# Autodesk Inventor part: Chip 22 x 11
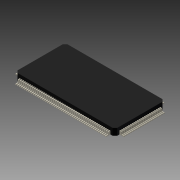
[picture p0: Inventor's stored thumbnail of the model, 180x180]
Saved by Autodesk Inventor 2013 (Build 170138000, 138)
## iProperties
Company: Autodesk Inc.
Created: 2005-12
Part Number: Chip 22 x 11
Document SubType Name: Modeling
Designer: Autodesk Inc.
Density: 1 g/cm^3
Mass: 0.375707 g
Surface Area: 7.692 cm^2
Volume: 0.375707 cm^3
Material: Allgemein
Title: Personal Computer
Author: Autodesk Inc.
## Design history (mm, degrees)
sketch "Sketch1"
  geometry: L1 (0, 7.7)-(0, -7.7) reference; L2 (-15.4, 0)-(15.4, 0) reference; L3 (-11, 5.5)-(11, 5.5); L4 (11, 5.5)-(11, -5.5); L5 (11, -5.5)-(-11, -5.5); L6 (-11, -5.5)-(-11, 5.5)
  constraints: 8 end point, 2 parallel, 1 horizontal, 1 perpendicular, 2 other
  dimensions: "d0" = 22 distance of L3.start L3.end; "d1" = 11 distance of L5.end L3.start
extrude "Extrusion1" new body sketch "Sketch1" distance "d2" = 1.5; taper "d3" = 0 deg
workplane "Work Plane1"
sketch "Sketch3"
  geometry: L1 (22, 0)-(22, 1.5) reference; L2 (22, 0)-(0, 0) reference; L3 (22, 0)-(23.221, 0); L4 (22, 0.75)-(22.317, 0.75); L5 (22.415, 0.668)-(22.485, 0.282); L6 (22.583, 0.2)-(22.85, 0.2); L7 (23, 0.05)-(23, 0); L8 (22, 0)-(23, 0); L9 (22, 0)-(22, 0.75); A1 r 0.1 centre (22.317, 0.65) between (22.415, 0.668) and (22.317, 0.75); A2 r 0.1 centre (22.583, 0.3) between (22.485, 0.282) and (22.583, 0.2); A3 r 0.15 centre (22.85, 0.05) between (23, 0.05) and (22.85, 0.2); 3 further points
  constraints: 14 end point, 7 point on line, 6 point on circle, 6 tangent, 3 centre point, 3 collinear, 2 parallel, 1 equal radius, 1 midpoint, 1 perpendicular
  dimensions: "d13" = 1 distance between parallel lines of L9 L7; "d14" = 0.4 distance of L4.start point (22.4, 0.75); "d15" = 0.2 distance of point (23, 0.2) L7.end; "d16" = 0.5 distance of point (22.5, 0.2) point (23, 0.2); "d17" = 0.1 radius of A1; "d18" = 0.15 radius of A3
extrude "Extrusion3" join sketch "Sketch3" distance "d19" = 0.2; taper "d20" = 0 deg
mirror "Mirror3"
workplane "Work Plane3"
sketch "Sketch5"
  geometry: L1 (1.5, 0)-(0, 0) reference; L2 (1.5, 1)-(1.5, 0) reference; L3 (1.5, 0)-(1.5, -1.562); L4 (0.75, 0)-(0.75, -0.317); L5 (0.832, -0.415)-(1.218, -0.485); L6 (1.3, -0.583)-(1.3, -0.85); L7 (1.45, -1)-(1.5, -1); L8 (1.5, 0)-(1.5, -1); L9 (0.75, 0)-(1.5, 0); A1 r 0.15 centre (1.45, -0.85) between (1.3, -0.85) and (1.45, -1); A2 r 0.1 centre (0.85, -0.317) between (0.75, -0.317) and (0.832, -0.415); A3 r 0.1 centre (1.2, -0.583) between (1.3, -0.583) and (1.218, -0.485); 3 further points
  constraints: 14 end point, 7 point on line, 6 point on circle, 6 tangent, 3 centre point, 3 collinear, 2 parallel, 1 equal radius, 1 midpoint, 1 perpendicular
  dimensions: "d25" = 0.2 distance of point (1.3, -1) L7.end; "d26" = 0.5 distance of point (1.3, -0.5) point (1.3, -1); "d27" = 0.4 distance of L4.start point (0.75, -0.4); "d28" = 1 distance between parallel lines of L1 L7; "d29" = 0.15 radius of A1; "d30" = 0.1 radius of A2
extrude "Extrusion4" join sketch "Sketch5" distance "d31" = 0.2; taper "d32" = 0 deg
mirror "Mirror4"
chamfer "Chamfer1" distance "d36" = 0.5; stored, may be unused: second distance "d37" = 2, angle "d38" = 45 deg
body "Solid1"
pattern_linear "Rectangular Pattern2" dims "d23" = 8.8
pattern_linear "Rectangular Pattern3" dims "d35" = 19.8
other parameters: "d4" = -1, "d24" = -1
